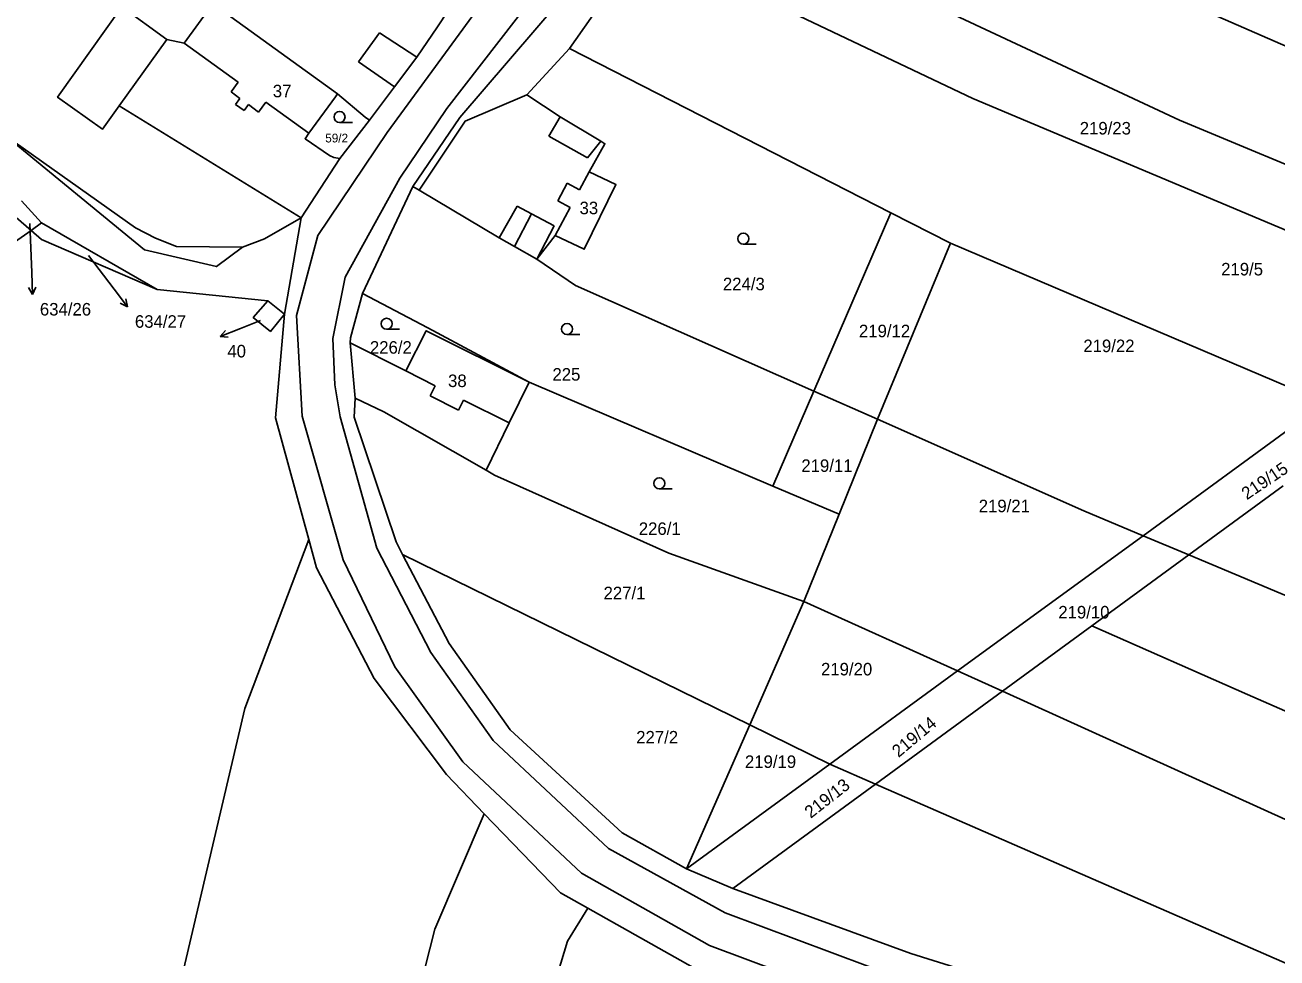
# Model space of a CAD drawing. Extents: x -746176 to -739709, y -1128407 to -1124482.
# Drawn here: x -743087.7 to -742917.8, y -1127796.2 to -1127669.6 of the extents above; entities that cross this region are included whole.
import ezdxf

# ---------------------------------------------------------------- set-up
doc = ezdxf.new("R2010")
doc.units = 0
for name, color, linetype in [('Hranice parcel', 7, 'Continuous'), ('Parcelní čísla', 7, 'Continuous'), ('Pop  PČ popisy', 7, 'Continuous'), ('Vnitřní kresba', 7, 'Continuous'), ('Značky kultur', 7, 'Continuous')]:
    doc.layers.add(name, color=color, linetype=linetype)

msp = doc.modelspace()

# ---------------------------------------------------------------- linework, layer by layer
at = {"layer": 'Hranice parcel'}
for p, q in [((-743013.81, -1127672.8), (-743003.07, -1127657.38)), ((-743045.29, -1127678.95), (-743062.24, -1127666.73)), ((-743019.62, -1127679.08), (-743013.81, -1127672.8)), ((-743013.81, -1127672.8), (-742970.18, -1127695.1)), ((-743040.96, -1127682.5), (-743044.97, -1127687.73)), ((-743044.97, -1127687.73), (-743050.26, -1127695.79)), ((-743035.1, -1127691.53), (-743041.92, -1127706.05)), ((-743035.1, -1127691.53), (-743034.24, -1127692.03)), ((-743088.2, -1127693.47), (-743085.48, -1127696.45)), ((-743086.91, -1127697.47), (-743089.62, -1127695.12)), ((-743050.26, -1127695.79), (-743052.52, -1127708.86)), ((-742970.18, -1127695.1), (-742980.63, -1127719.3)), ((-742970.18, -1127695.1), (-742962.09, -1127699.23)), ((-743086.91, -1127697.47), (-743085.48, -1127696.45)), ((-743085.48, -1127696.45), (-743069.79, -1127705.5)), ((-742972.01, -1127723.11), (-742962.09, -1127699.23)), ((-742962.09, -1127699.23), (-742911.19, -1127720.85)), ((-743054.75, -1127707.06), (-743069.79, -1127705.5)), ((-743054.75, -1127707.06), (-743052.52, -1127708.86)), ((-743042.89, -1127720.23), (-743043.57, -1127712.76)), ((-743019.3, -1127718.08), (-742986.19, -1127732.18)), ((-742980.63, -1127719.3), (-742986.19, -1127732.18)), ((-742972.01, -1127723.11), (-742980.63, -1127719.3)), ((-742911.19, -1127720.85), (-742935.96, -1127738.92)), ((-742977.22, -1127736), (-742972.01, -1127723.11)), ((-742986.19, -1127732.18), (-742977.22, -1127736)), ((-742916.95, -1127732.14), (-742929.76, -1127741.52)), ((-742977.22, -1127736), (-742982, -1127747.83)), ((-742935.96, -1127738.92), (-742961.12, -1127757.28)), ((-742929.76, -1127741.52), (-742935.96, -1127738.92)), ((-743036.47, -1127741.45), (-742989.35, -1127764.58)), ((-742942.9, -1127751.14), (-742929.76, -1127741.52)), ((-742982, -1127747.83), (-742989.35, -1127764.58)), ((-742961.12, -1127757.28), (-742982, -1127747.83)), ((-742955.04, -1127760.03), (-742942.9, -1127751.14)), ((-742961.12, -1127757.28), (-742978.46, -1127769.93)), ((-742961.12, -1127757.28), (-742955.04, -1127760.03)), ((-742955.04, -1127760.03), (-742972.27, -1127772.64)), ((-742989.35, -1127764.58), (-742997.92, -1127784.13)), ((-742978.46, -1127769.93), (-742989.35, -1127764.58)), ((-742978.46, -1127769.93), (-742997.92, -1127784.13)), ((-742972.27, -1127772.64), (-742978.46, -1127769.93)), ((-742972.27, -1127772.64), (-742991.64, -1127786.82)), ((-742833.19, -1127833.4), (-742972.27, -1127772.64)), ((-742991.64, -1127786.82), (-742997.92, -1127784.13)), ((-743011.33, -1127789.48), (-742996.28, -1127797.93))]:
    msp.add_line(p, q, dxfattribs=at)
for points in [[(-742984.29, -1127611.5), (-742990.11, -1127623.65), (-743005.02, -1127654.54), (-743028.72, -1127682.17), (-743035.1, -1127691.53)], [(-742989.43, -1127637.82), (-742962.79, -1127651.94), (-742947.37, -1127659.01), (-742888.66, -1127684.65), (-742875.08, -1127689.31), (-742869.86, -1127690.69)], [(-742884.93, -1127701.69), (-742931.01, -1127682.52), (-742982.33, -1127658.51), (-742997.69, -1127649.67)], [(-742892.82, -1127707.45), (-742959.07, -1127679.57), (-742986.2, -1127666.67), (-743003.07, -1127657.38)], [(-743026.2, -1127661.44), (-743031.72, -1127669.85), (-743034.56, -1127673.98), (-743037.58, -1127678), (-743040.96, -1127682.5)], [(-743050.26, -1127695.79), (-743074.95, -1127680.59), (-743077.21, -1127683.74), (-743083.3, -1127679.41), (-743074.6, -1127667.14), (-743068.46, -1127671.55), (-743066.13, -1127672.07), (-743062.24, -1127666.73)], [(-743044.97, -1127687.73), (-743045.79, -1127687.59), (-743046.39, -1127687.31), (-743049.72, -1127685.03), (-743049.19, -1127684.3), (-743045.58, -1127679.36), (-743045.29, -1127678.95)], [(-743045.29, -1127678.95), (-743041.53, -1127682.11), (-743040.96, -1127682.5)], [(-743034.24, -1127692.03), (-743027.99, -1127682.66), (-743019.62, -1127679.08)], [(-743019.62, -1127679.08), (-743015.08, -1127682.06), (-743009.56, -1127685.38), (-743009, -1127685.72), (-743011.13, -1127689.55), (-743007.52, -1127691.27), (-743011.82, -1127700.03), (-743015.78, -1127698.17), (-743018.27, -1127701.4)], [(-743090.48, -1127684.56), (-743071.53, -1127700.11), (-743061.74, -1127702.4), (-743058.22, -1127699.76)], [(-743018.27, -1127701.4), (-743021.3, -1127699.65), (-743023.34, -1127698.47), (-743034.24, -1127692.03)], [(-743058.22, -1127699.76), (-743055.21, -1127698.61), (-743050.26, -1127695.79)], [(-743086.91, -1127697.47), (-743090.95, -1127700.36), (-743100.45, -1127723.29), (-743120.32, -1127804.45), (-743137.57, -1127875.6)], [(-743069.79, -1127705.5), (-743085.49, -1127698.7), (-743086.91, -1127697.47)], [(-743018.27, -1127701.4), (-743013, -1127704.97), (-742980.63, -1127719.3)], [(-743043.57, -1127712.76), (-743043.55, -1127712.08), (-743041.92, -1127706.05)], [(-743041.92, -1127706.05), (-743033.05, -1127710.69), (-743019.3, -1127718.08)], [(-743052.52, -1127708.86), (-743054.42, -1127711.2), (-743056.75, -1127709.3), (-743054.75, -1127707.06)], [(-743049.21, -1127739.41), (-743053.72, -1127722.94), (-743052.52, -1127708.86)], [(-743019.3, -1127718.08), (-743033.26, -1127711.09), (-743036.05, -1127716.56), (-743043.57, -1127712.76)], [(-743025.14, -1127730.02), (-743022, -1127723.61), (-743019.3, -1127718.08)], [(-743036.47, -1127741.45), (-743037.36, -1127739.74), (-743043.04, -1127722.81), (-743042.89, -1127720.23)], [(-743025.14, -1127730.02), (-743039.01, -1127722.1), (-743042.89, -1127720.23)], [(-742935.96, -1127738.92), (-742943.98, -1127735.55), (-742972.01, -1127723.11)], [(-742982, -1127747.83), (-743000.34, -1127741.31), (-743023.98, -1127730.68), (-743025.14, -1127730.02)], [(-743134.48, -1128101.6), (-743116.84, -1128032.47), (-743112.87, -1128006.6), (-743093.99, -1127930.3), (-743081.3, -1127862.06), (-743057.88, -1127762.39), (-743049.21, -1127739.41)], [(-743049.21, -1127739.41), (-743048.14, -1127743.3), (-743040.35, -1127758.3), (-743030.5, -1127771.33), (-743025.38, -1127776.65)], [(-742997.92, -1127784.13), (-743006.65, -1127779.24), (-743021.89, -1127765.25), (-743030.16, -1127753.57), (-743036.47, -1127741.45)], [(-742929.76, -1127741.52), (-742892.25, -1127757.26), (-742839.56, -1127779.37), (-742839.56, -1127777.92), (-742777.16, -1127805.95), (-742712.92, -1127837.01)], [(-742942.9, -1127751.14), (-742921.78, -1127760.46), (-742847.12, -1127793.15), (-742812.02, -1127809), (-742724.3, -1127849.19), (-742701.43, -1127856.81), (-742666.84, -1127871.89)], [(-742670.28, -1127883.77), (-742733.59, -1127858.01), (-742796.71, -1127830.89), (-742912.22, -1127779.41), (-742955.04, -1127760.03)], [(-743103, -1128100.87), (-743064.96, -1127935.44), (-743045.29, -1127844.24), (-743032.09, -1127792.31), (-743025.38, -1127776.65)], [(-743025.38, -1127776.65), (-743015.05, -1127787.39), (-743011.33, -1127789.48)], [(-742830.43, -1127861.03), (-742831.55, -1127859.78), (-742848.33, -1127844.01), (-742864.61, -1127832.85), (-742882.56, -1127824.07), (-742889.66, -1127821.18), (-742902.77, -1127815.89), (-742967.48, -1127795.61), (-742991.64, -1127786.82)], [(-743087.22, -1128100.5), (-743078.12, -1128059.75), (-743051.52, -1127944.14), (-743026.17, -1127833.83), (-743014.07, -1127793.96), (-743011.33, -1127789.48)]]:
    msp.add_lwpolyline(points, dxfattribs=at)
at = {"layer": 'Pop  PČ popisy'}
for p, q in [((-743087.06, -1127696.52), (-743086.82, -1127703.2)), ((-743079.13, -1127700.88), (-743075.63, -1127705.47)), ((-743086.82, -1127703.2), (-743086.71, -1127706.2)), ((-743086.71, -1127706.2), (-743087.25, -1127705.22)), ((-743086.71, -1127706.2), (-743086.25, -1127705.18)), ((-743075.63, -1127705.47), (-743073.82, -1127707.87)), ((-743073.82, -1127707.87), (-743074.83, -1127707.37)), ((-743073.82, -1127707.87), (-743074.03, -1127706.77)), ((-743055.74, -1127709.69), (-743058.47, -1127710.78)), ((-743058.47, -1127710.78), (-743061.25, -1127711.9)), ((-743061.25, -1127711.9), (-743060.51, -1127711.06)), ((-743061.25, -1127711.9), (-743060.14, -1127711.99))]:
    msp.add_line(p, q, dxfattribs=at)
at = {"layer": 'Vnitřní kresba'}
for p, q in [((-743030.45, -1127680.95), (-743007.93, -1127651.85)), ((-743038.55, -1127684.18), (-743020.57, -1127659.55)), ((-743042.45, -1127674.62), (-743039.6, -1127670.68)), ((-743039.6, -1127670.68), (-743034.56, -1127673.98)), ((-743074.95, -1127680.59), (-743068.46, -1127671.55)), ((-743066.13, -1127672.07), (-743058.8, -1127677.37)), ((-743042.45, -1127674.62), (-743037.58, -1127678)), ((-743059.75, -1127678.69), (-743058.8, -1127677.37)), ((-743059.75, -1127678.69), (-743058.57, -1127679.56)), ((-743059.15, -1127680.38), (-743058.57, -1127679.56)), ((-743059.15, -1127680.38), (-743057.98, -1127681.22)), ((-743057.98, -1127681.22), (-743057.39, -1127680.41)), ((-743057.39, -1127680.41), (-743056.02, -1127681.41)), ((-743056.02, -1127681.41), (-743055.05, -1127680.07)), ((-743055.05, -1127680.07), (-743049.19, -1127684.3)), ((-743036.85, -1127690.37), (-743030.45, -1127680.95)), ((-743016.62, -1127684.69), (-743015.08, -1127682.06)), ((-743047.98, -1127698.19), (-743038.55, -1127684.18)), ((-743090.48, -1127684.56), (-743072.72, -1127697.13)), ((-743016.62, -1127684.69), (-743011.36, -1127687.63)), ((-743011.36, -1127687.63), (-743009.56, -1127685.38)), ((-743044.25, -1127703.82), (-743036.85, -1127690.37)), ((-743015.4, -1127693.46), (-743014.15, -1127691.05)), ((-743014.15, -1127691.05), (-743012.44, -1127691.97)), ((-743012.44, -1127691.97), (-743011.13, -1127689.55)), ((-743023.34, -1127698.47), (-743020.92, -1127694.17)), ((-743020.92, -1127694.17), (-743018.97, -1127695.22)), ((-743015.78, -1127698.17), (-743013.73, -1127694.36)), ((-743015.4, -1127693.46), (-743013.73, -1127694.36)), ((-743021.3, -1127699.65), (-743018.97, -1127695.22)), ((-743018.97, -1127695.22), (-743015.9, -1127696.88)), ((-743072.72, -1127697.13), (-743070.01, -1127698.54)), ((-743018.27, -1127701.4), (-743015.9, -1127696.88)), ((-743070.01, -1127698.54), (-743067.17, -1127699.66)), ((-743067.17, -1127699.66), (-743058.22, -1127699.76)), ((-743050.88, -1127709.04), (-743047.98, -1127698.19)), ((-743045.96, -1127712.14), (-743044.25, -1127703.82)), ((-743050.88, -1127709.04), (-743050.12, -1127722.67)), ((-743045.96, -1127712.14), (-743045.67, -1127718.43)), ((-743036.05, -1127716.56), (-743032.05, -1127718.56)), ((-743045.67, -1127718.43), (-743044.96, -1127722.78)), ((-743032.75, -1127719.95), (-743032.05, -1127718.56)), ((-743032.75, -1127719.95), (-743028.9, -1127721.9)), ((-743028.9, -1127721.9), (-743028.19, -1127720.5)), ((-743028.19, -1127720.5), (-743022, -1127723.61)), ((-743050.12, -1127722.67), (-743044.56, -1127742.19)), ((-743044.96, -1127722.78), (-743039.98, -1127740.62)), ((-743044.56, -1127742.19), (-743037.53, -1127756.7)), ((-743039.98, -1127740.62), (-743032.62, -1127754.77)), ((-743032.62, -1127754.77), (-743024.19, -1127766.7)), ((-743037.53, -1127756.7), (-743028.31, -1127769.6)), ((-743024.19, -1127766.7), (-743008.52, -1127781.37)), ((-743028.31, -1127769.6), (-743012.17, -1127784.72)), ((-743008.52, -1127781.37), (-742992.69, -1127790.12)), ((-743012.17, -1127784.72), (-742994.83, -1127794.53)), ((-742992.69, -1127790.12), (-742968.49, -1127799.16)), ((-742994.83, -1127794.53), (-742969.96, -1127803.78))]:
    msp.add_line(p, q, dxfattribs=at)
at = {"layer": 'Značky kultur'}
for p, q in [((-743045.03, -1127682.83), (-743043.28, -1127682.83)), ((-742990.21, -1127699.35), (-742988.46, -1127699.35)), ((-743038.64, -1127710.9), (-743036.89, -1127710.9)), ((-743014.15, -1127711.62), (-743012.4, -1127711.62)), ((-743001.63, -1127732.56), (-742999.88, -1127732.56))]:
    msp.add_line(p, q, dxfattribs=at)
for centre in [(-743045.03, -1127682.08), (-742990.21, -1127698.6), (-743038.64, -1127710.15), (-743014.15, -1127710.87), (-743001.63, -1127731.81)]:
    msp.add_circle(centre, 0.75, dxfattribs=at)

# ---------------------------------------------------------------- texts
at = {"layer": 'Parcelní čísla'}
for s, height, p in [('37', 1.7, (-743054.09, -1127679.41)), ('219/23', 1.7, (-742944.55, -1127684.46)), ('59/2', 1.19, (-743046.97, -1127685.54)), ('33', 1.7, (-743012.45, -1127695.28)), ('219/5', 1.7, (-742925.35, -1127703.59)), ('224/3', 1.7, (-742992.99, -1127705.6)), ('634/26', 1.7, (-743085.71, -1127709.03)), ('634/27', 1.7, (-743072.81, -1127710.69)), ('219/12', 1.7, (-742974.52, -1127711.98)), ('40', 1.7, (-743060.26, -1127714.72)), ('226/2', 1.7, (-743040.91, -1127714.21)), ('219/22', 1.7, (-742944.06, -1127714)), ('225', 1.7, (-743016.13, -1127717.87)), ('38', 1.7, (-743030.3, -1127718.74)), ('219/11', 1.7, (-742982.34, -1127730.26)), ('219/21', 1.7, (-742958.26, -1127735.73)), ('226/1', 1.7, (-743004.41, -1127738.81)), ('227/1', 1.7, (-743009.19, -1127747.54)), ('219/10', 1.7, (-742947.46, -1127750.15)), ('219/20', 1.7, (-742979.67, -1127757.88)), ('227/2', 1.7, (-743004.76, -1127767.12)), ('219/19', 1.7, (-742990, -1127770.44))]:
    msp.add_text(s, height=height, dxfattribs=at).set_placement(p)
for s, rotation, p in [('219/15', 34, (-742921.86, -1127734.11)), ('219/14', 40, (-742969.15, -1127769.1)), ('219/13', 38, (-742981.07, -1127777.36))]:
    msp.add_text(s, height=1.7, rotation=rotation, dxfattribs=at).set_placement(p)

doc.saveas('drawing.dxf')
